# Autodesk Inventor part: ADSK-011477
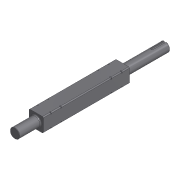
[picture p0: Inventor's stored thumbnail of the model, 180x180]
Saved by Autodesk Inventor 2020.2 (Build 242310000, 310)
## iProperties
Created: 1999-08
Part Number: ADSK-011477
Description: SHFTSP,FC,AX,010,157,022,045,SQ,TAIL,CONV,KEYD
Material: RA CRS
Document SubType Name: Modeling
Designer: MP
Density: 7.83 g/cm^3
Appearance: Metal-Steel(Polish)
Mass: 3233 g
Surface Area: 500.74 cm^2
Volume: 412.899 cm^3
Control State: 0
Master: False
Checked Out: False
Shininess: 0.0
Length Units: 11269
Angle Units: 11279
Time Units: 11290
Mass Units: 11283
Length Display Precision: 3
Angle Display Precision: 2
Compacted: True
Cutlength: 15.75
Material Desc: FLAT,CRS,1.500X1.500
Material_Number: A084149
Dimensions: 38x400x38 mm
Mass: 3,233 kg
VLT_Material: RA CRS
DocNumber: ADSK-011477.ipt
Folder: 01 - Themengebiete\Simplification\01 - Packaging machine\
VDS_Category: 3D Komponenten
Density: 0.0
Volumn: 0.0
Area: 0.0
PropertySet Name: Model Information
Author: MP
Revision Number: -
Title: shaft
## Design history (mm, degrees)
node "Extrusion1" dims "d6" = 229, "d7" = 0
  sketch "Sketch1"
    geometry: L1 (-16.857, -19)-(16.857, -19); L2 (19, -16.857)-(19, 16.857); L3 (16.857, 19)-(-16.857, 19); L4 (-19, 16.857)-(-19, -16.857); A1 r 25.4 centre (0, 0) between (-16.857, 19) and (-19, 16.857); A2 r 25.4 centre (0, 0) between (19, 16.857) and (16.857, 19); A3 r 25.4 centre (0, 0) between (-19, -16.857) and (-16.857, -19); A4 r 25.4 centre (0, 0) between (16.857, -19) and (19, -16.857); 1 further point
    constraints: 8 end point, 8 point on circle, 4 centre point, 4 parallel, 3 concentric, 1 coincident, 1 horizontal, 1 perpendicular
    dimensions: "d12" = 25.4 radius of A2; "d41" = 38 distance between parallel lines of L1 L3; "d42" = 38 distance between parallel lines of L2 L4 (= d41)
node "Extrusion2" dims "d9" = 57, "d10" = 0
  sketch "Sketch2"
    geometry: C1 r 12.7 at (0, 0)
    constraints: 1 centre point
    dimensions: "d8" = 25.4 diameter of C1
node "Extrusion5" dims "d25" = 114, "d26" = 0
  sketch "Sketch4"
    geometry: C1 r 12.5 at (0, 0); A1 r 25.4 centre (0, 0) between (16.857, -19) and (19, -16.857) reference
    constraints: 1 centre point, 1 coincident
    dimensions: "d24" = 25 diameter of C1
workplane "Work Plane2"
node "Extrusion6" dims "d33" = 3, "d34" = 0
  sketch "Sketch5"
    geometry: L1 (12.5, -114)-(-12.5, -114) reference; L2 (-3, -114)-(3, -114); L3 (3, -114)-(3, -79); L4 (-3, -79)-(-3, -114); L5 (0, -114)-(0, -79) reference; A1 r 3 centre (0, -79) between (3, -79) and (-3, -79)
    constraints: 8 end point, 2 point on circle, 1 centre point, 1 coincident, 1 horizontal, 1 midpoint, 1 parallel, 1 perpendicular, 1 point on line, 1 tangent, 1 vertical
    dimensions: "d31" = 3 distance between parallel lines of L3 L5; "d32" = 35 distance of L2.end L3.end
workplane "Work Plane1"
node "Extrusion4" dims "d19" = 2.2, "d20" = 0
  sketch "Sketch3"
    geometry: L1 (-16.857, 19)-(16.857, 19) reference; L2 (-19, -16.857)-(-19, 16.857) reference; L3 (19, 16.857)-(19, -16.857) reference; L4 (16.857, -19)-(-16.857, -19) reference; C1 r 24.13 at (0, 0); 1 further point
    constraints: 1 centre point, 1 coincident, 3 other
    dimensions: "d18" = 48.26 diameter of C1
node "Mirror2"
node "Fillet1" dims "d21" = 3
node "Chamfer1" dims "d22" = 1, "d23" = 1, "d40" = 45 deg
workplane "Work Plane4"
node "Extrusion7" dims "d36" = 0, "d37" = 2.2
  sketch "Sketch6"
    geometry: C1 r 25.4 at (0, 0); C2 r 24.13 at (0, 0); A1 r 25.4 centre (0, 0) between (-16.857, 19) and (-19, 16.857) reference; A2 r 25.4 centre (0, 0) between (-16.857, 19) and (-19, 16.857) reference
    constraints: 2 centre point, 1 coincident, 1 concentric
    dimensions: "d38" = 48.26 diameter of C2
workplane "Work Plane5"
node "Mirror3"
workplane "Arbeitsebene7"
workplane "Arbeitsebene8"
node "Solide1"
node "Corps solides"
node "Corps surfaciques"
node "Projizierte Kontur1"
other parameters: "d11" = 50.8, "d13" = 93.1164, "d14" = 48.26, "d35" = -48.768, "d39" = -114.3
